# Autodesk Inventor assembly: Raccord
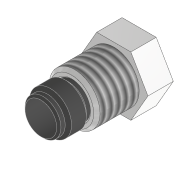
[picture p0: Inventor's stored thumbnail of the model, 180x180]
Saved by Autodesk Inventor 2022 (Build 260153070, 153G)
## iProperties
Created: 2021-07
Part Number: Raccord
Document SubType Name: Assembly
Designer: Fabian
Author: Fabian
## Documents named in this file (3)
- C:\Users\Fabian\Google Drive\01_Giup\01_Clients\07_ENI\Manuscrit\Fichiers_exercice\Chapitre_06\Exercice_liaison\Raccord.iam
- C:\Users\Fabian\Google Drive\01_Giup\01_Clients\07_ENI\Manuscrit\Fichiers_exercice\Chapitre_06\Exercice_contrainte\Vis.ipt
- C:\Users\Fabian\Google Drive\01_Giup\01_Clients\07_ENI\Manuscrit\Fichiers_exercice\Chapitre_06\Exercice_contrainte\Bague.ipt
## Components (2 placed, 2 different names)
1. Vis:1 — Logement:1
2. Bague:1 — Logement:1
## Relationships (1: Insert 1)
- Logement:1 [Insert]: Vis:1 ↔ Bague:1
